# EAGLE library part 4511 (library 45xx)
BCD to 7-segment LATCH/DECODER/DRIVER
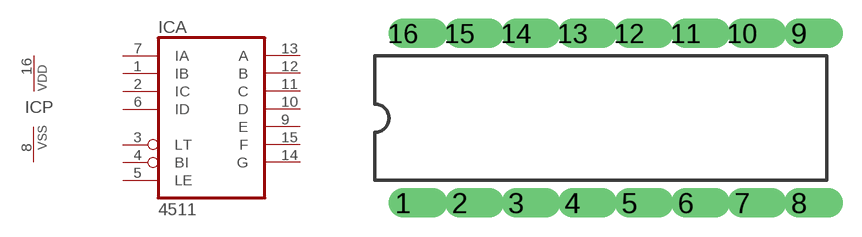
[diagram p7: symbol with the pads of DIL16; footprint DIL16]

Designator prefix IC; gates A=4511 P=PWRN

## 4511N  [DIL16]
1  A:IB  in
2  A:IC  in
3  A:LT  in
4  A:BI  in
5  A:LE  in
6  A:ID  in
7  A:IA  in
8  P:VSS  pwr
9  A:E  out
10  A:D  out
11  A:C  out
12  A:B  out
13  A:A  out
14  A:G  out
15  A:F  out
16  P:VDD  pwr

## Footprint DIL16 (pad centres in mm)
Dual In Line
drill 0.813 offset: 1 -8.89,-3.81; 2 -6.35,-3.81; 3 -3.81,-3.81; 4 -1.27,-3.81; 5 1.27,-3.81; 6 3.81,-3.81; 7 6.35,-3.81; 8 8.89,-3.81; 9 8.89,3.81; 10 6.35,3.81; 11 3.81,3.81; 12 1.27,3.81; 13 -1.27,3.81; 14 -3.81,3.81; 15 -6.35,3.81; 16 -8.89,3.81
